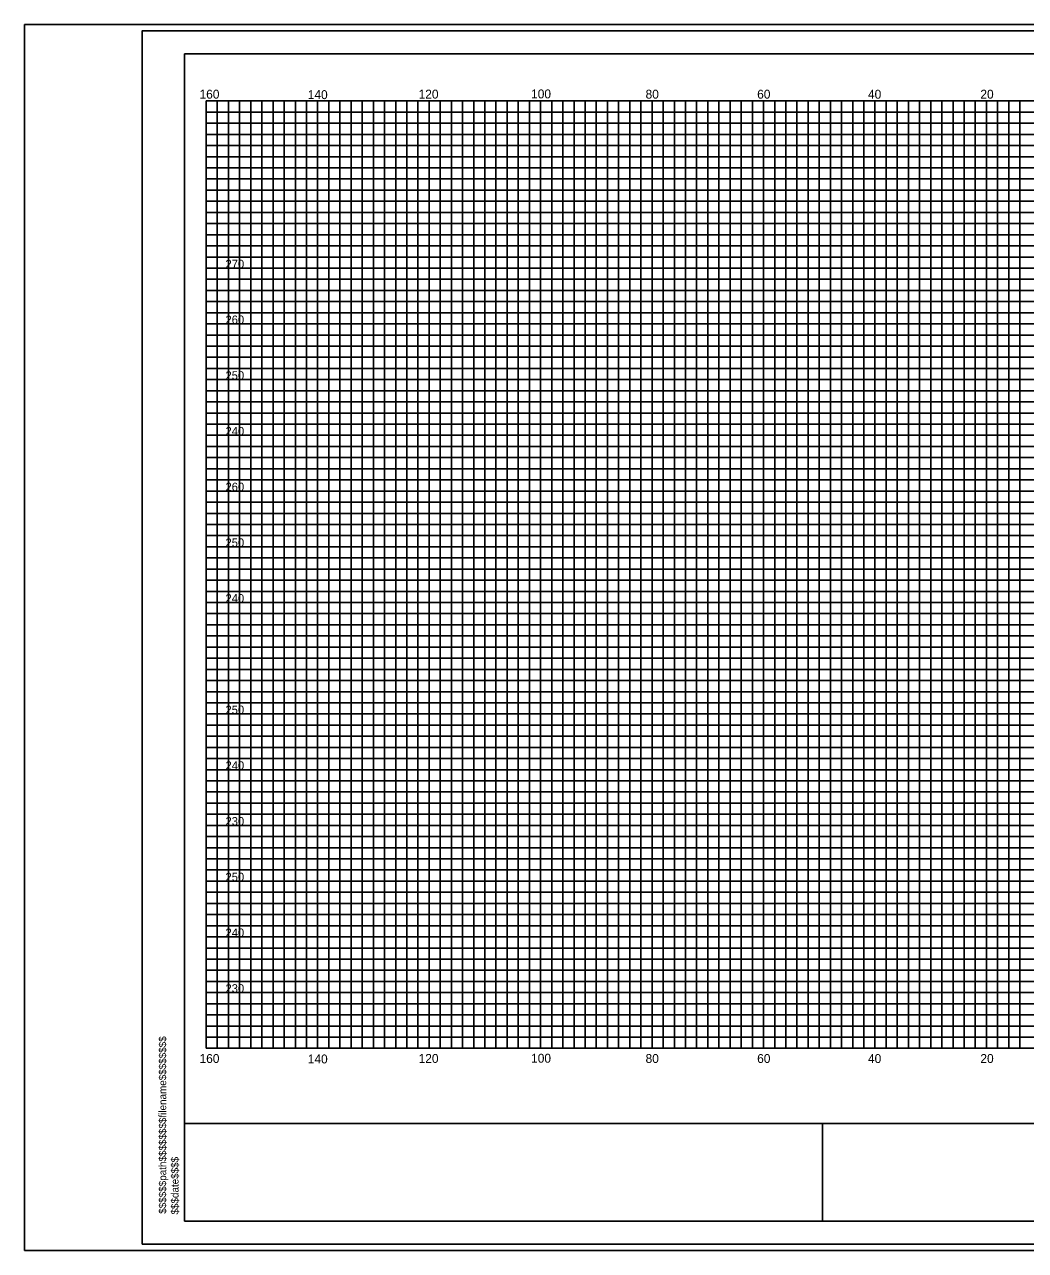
# Model space of a CAD drawing. Extents: x 967 to 1326, y 964 to 3704.
# Drawn here: x 967.4 to 1147, y 963.7 to 1183.7 of the extents above; entities that cross this region are included whole.
import ezdxf

# ---------------------------------------------------------------- set-up
doc = ezdxf.new("R2010")
doc.units = 0
for name, color, linetype in [('Default', 7, 'Continuous'), ('RD_SHT_Bndy', 7, 'Continuous'), ('RD_SHT_IplotShp', 7, 'Continuous'), ('RD_SHT_MjGrid', 7, 'Continuous'), ('RD_SHT_MnGrid', 7, 'Continuous'), ('RD_SHT_TX', 7, 'Continuous'), ('RD_XS_TX_Station', 7, 'Continuous')]:
    doc.layers.add(name, color=color, linetype=linetype)

msp = doc.modelspace()

# ---------------------------------------------------------------- linework, layer by layer
at = {"layer": 'RD_SHT_Bndy'}
for p, q in [((996.11, 968.98), (996.11, 1178.46)), ((996.11, 1178.46), (1323.89, 1178.46)), ((996.11, 986.49), (1323.89, 986.49)), ((1110.59, 968.98), (1110.59, 986.56)), ((1323.89, 968.98), (996.11, 968.98))]:
    msp.add_line(p, q, dxfattribs=at)
at = {"layer": 'RD_SHT_IplotShp'}
for points in [[(967.41, 963.72), (1326.28, 963.72), (1326.28, 1183.72), (967.41, 1183.72)], [(988.52, 964.84), (1326.28, 964.84), (1326.28, 1182.6), (988.52, 1182.6)]]:
    msp.add_lwpolyline(points, close=True, dxfattribs=at)
at = {"layer": 'RD_SHT_MjGrid'}
for p, q in [((1000, 1170), (1320, 1170)), ((1000, 1000), (1000, 1170)), ((1010, 1000), (1010, 1170)), ((1020, 1000), (1020, 1170)), ((1030, 1000), (1030, 1170)), ((1040, 1000), (1040, 1170)), ((1050, 1000), (1050, 1170)), ((1060, 1000), (1060, 1170)), ((1070, 1000), (1070, 1170)), ((1080, 1000), (1080, 1170)), ((1090, 1000), (1090, 1170)), ((1100, 1000), (1100, 1170)), ((1110, 1000), (1110, 1170)), ((1120, 1000), (1120, 1170)), ((1130, 1000), (1130, 1170)), ((1140, 1000), (1140, 1170)), ((1000, 1160), (1320, 1160)), ((1000, 1150), (1320, 1150)), ((1000, 1140), (1320, 1140)), ((1000, 1130), (1320, 1130)), ((1000, 1120), (1320, 1120)), ((1000, 1110), (1320, 1110)), ((1000, 1100), (1320, 1100)), ((1000, 1090), (1320, 1090)), ((1000, 1080), (1320, 1080)), ((1000, 1070), (1320, 1070)), ((1000, 1060), (1320, 1060)), ((1000, 1050), (1320, 1050)), ((1000, 1040), (1320, 1040)), ((1000, 1030), (1320, 1030)), ((1000, 1020), (1320, 1020)), ((1000, 1010), (1320, 1010)), ((1000, 1000), (1320, 1000))]:
    msp.add_line(p, q, dxfattribs=at)
at = {"layer": 'RD_SHT_MnGrid'}
for p, q in [((1002, 1000), (1002, 1170)), ((1004, 1000), (1004, 1170)), ((1006, 1000), (1006, 1170)), ((1008, 1000), (1008, 1170)), ((1012, 1000), (1012, 1170)), ((1014, 1000), (1014, 1170)), ((1016, 1000), (1016, 1170)), ((1018, 1000), (1018, 1170)), ((1022, 1000), (1022, 1170)), ((1024, 1000), (1024, 1170)), ((1026, 1000), (1026, 1170)), ((1028, 1000), (1028, 1170)), ((1032, 1000), (1032, 1170)), ((1034, 1000), (1034, 1170)), ((1036, 1000), (1036, 1170)), ((1038, 1000), (1038, 1170)), ((1042, 1000), (1042, 1170)), ((1044, 1000), (1044, 1170)), ((1046, 1000), (1046, 1170)), ((1048, 1000), (1048, 1170)), ((1052, 1000), (1052, 1170)), ((1054, 1000), (1054, 1170)), ((1056, 1000), (1056, 1170)), ((1058, 1000), (1058, 1170)), ((1062, 1000), (1062, 1170)), ((1064, 1000), (1064, 1170)), ((1066, 1000), (1066, 1170)), ((1068, 1000), (1068, 1170)), ((1072, 1000), (1072, 1170)), ((1074, 1000), (1074, 1170)), ((1076, 1000), (1076, 1170)), ((1078, 1000), (1078, 1170)), ((1082, 1000), (1082, 1170)), ((1084, 1000), (1084, 1170)), ((1086, 1000), (1086, 1170)), ((1088, 1000), (1088, 1170)), ((1092, 1000), (1092, 1170)), ((1094, 1000), (1094, 1170)), ((1096, 1000), (1096, 1170)), ((1098, 1000), (1098, 1170)), ((1102, 1000), (1102, 1170)), ((1104, 1000), (1104, 1170)), ((1106, 1000), (1106, 1170)), ((1108, 1000), (1108, 1170)), ((1112, 1000), (1112, 1170)), ((1114, 1000), (1114, 1170)), ((1116, 1000), (1116, 1170)), ((1118, 1000), (1118, 1170)), ((1122, 1000), (1122, 1170)), ((1124, 1000), (1124, 1170)), ((1126, 1000), (1126, 1170)), ((1128, 1000), (1128, 1170)), ((1132, 1000), (1132, 1170)), ((1134, 1000), (1134, 1170)), ((1136, 1000), (1136, 1170)), ((1138, 1000), (1138, 1170)), ((1142, 1000), (1142, 1170)), ((1144, 1000), (1144, 1170)), ((1146, 1000), (1146, 1170)), ((1000, 1168), (1320, 1168)), ((1000, 1166), (1320, 1166)), ((1000, 1164), (1320, 1164)), ((1000, 1162), (1320, 1162)), ((1000, 1158), (1320, 1158)), ((1000, 1156), (1320, 1156)), ((1000, 1154), (1320, 1154)), ((1000, 1152), (1320, 1152)), ((1000, 1148), (1320, 1148)), ((1000, 1146), (1320, 1146)), ((1000, 1144), (1320, 1144)), ((1000, 1142), (1320, 1142)), ((1000, 1138), (1320, 1138)), ((1000, 1136), (1320, 1136)), ((1000, 1134), (1320, 1134)), ((1000, 1132), (1320, 1132)), ((1000, 1128), (1320, 1128)), ((1000, 1126), (1320, 1126)), ((1000, 1124), (1320, 1124)), ((1000, 1122), (1320, 1122)), ((1000, 1118), (1320, 1118)), ((1000, 1116), (1320, 1116)), ((1000, 1114), (1320, 1114)), ((1000, 1112), (1320, 1112)), ((1000, 1108), (1320, 1108)), ((1000, 1106), (1320, 1106)), ((1000, 1104), (1320, 1104)), ((1000, 1102), (1320, 1102)), ((1000, 1098), (1320, 1098)), ((1000, 1096), (1320, 1096)), ((1000, 1094), (1320, 1094)), ((1000, 1092), (1320, 1092)), ((1000, 1088), (1320, 1088)), ((1000, 1086), (1320, 1086)), ((1000, 1084), (1320, 1084)), ((1000, 1082), (1320, 1082)), ((1000, 1078), (1320, 1078)), ((1000, 1076), (1320, 1076)), ((1000, 1074), (1320, 1074)), ((1000, 1072), (1320, 1072)), ((1000, 1068), (1320, 1068)), ((1000, 1066), (1320, 1066)), ((1000, 1064), (1320, 1064)), ((1000, 1062), (1320, 1062)), ((1000, 1058), (1320, 1058)), ((1000, 1056), (1320, 1056)), ((1000, 1054), (1320, 1054)), ((1000, 1052), (1320, 1052)), ((1000, 1048), (1320, 1048)), ((1000, 1046), (1320, 1046)), ((1000, 1044), (1320, 1044)), ((1000, 1042), (1320, 1042)), ((1000, 1038), (1320, 1038)), ((1000, 1036), (1320, 1036)), ((1000, 1034), (1320, 1034)), ((1000, 1032), (1320, 1032)), ((1000, 1028), (1320, 1028)), ((1000, 1026), (1320, 1026)), ((1000, 1024), (1320, 1024)), ((1000, 1022), (1320, 1022)), ((1000, 1018), (1320, 1018)), ((1000, 1016), (1320, 1016)), ((1000, 1014), (1320, 1014)), ((1000, 1012), (1320, 1012)), ((1000, 1008), (1320, 1008)), ((1000, 1006), (1320, 1006)), ((1000, 1004), (1320, 1004)), ((1000, 1002), (1320, 1002))]:
    msp.add_line(p, q, dxfattribs=at)
at = {"layer": 'RD_XS_TX_Station'}
msp.add_lwpolyline([(967.41, 963.72), (1326.28, 963.72), (1326.28, 1183.72), (967.41, 1183.72)], close=True, dxfattribs=at)

# ---------------------------------------------------------------- texts
at = {"layer": 'Default'}
for s, p in [('270', (1003.47, 1140)), ('260', (1003.47, 1130)), ('250', (1003.47, 1120)), ('240', (1003.47, 1110)), ('260', (1003.47, 1100)), ('250', (1003.47, 1090)), ('240', (1003.47, 1080)), ('250', (1003.47, 1060)), ('240', (1003.47, 1050)), ('230', (1003.47, 1040)), ('250', (1003.47, 1030)), ('240', (1003.47, 1020)), ('230', (1003.47, 1010))]:
    msp.add_text(s, height=1.5, dxfattribs=at).set_placement(p)
for s, p in [('$$$$$$path$$$$$$$$filename$$$$$$$$', (992.83, 970.31)), ('$$$date$$$$', (995.04, 970.17))]:
    msp.add_text(s, height=1.3258, rotation=90, dxfattribs=at).set_placement(p)
at = {"layer": 'RD_SHT_TX'}
for s, p in [('160', (998.81, 1170.42)), ('140', (1018.23, 1170.34)), ('120', (1038.12, 1170.43)), ('100', (1058.3, 1170.47)), ('80', (1078.84, 1170.42)), ('60', (1098.86, 1170.42)), ('40', (1118.75, 1170.41)), ('20', (1138.91, 1170.42)), ('160', (998.81, 997.37)), ('140', (1018.23, 997.29)), ('120', (1038.12, 997.38)), ('100', (1058.3, 997.42)), ('80', (1078.84, 997.37)), ('60', (1098.86, 997.37)), ('40', (1118.75, 997.36)), ('20', (1138.91, 997.37))]:
    msp.add_text(s, height=1.6, dxfattribs=at).set_placement(p)

doc.saveas('drawing.dxf')
